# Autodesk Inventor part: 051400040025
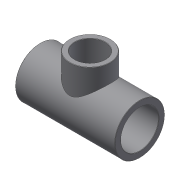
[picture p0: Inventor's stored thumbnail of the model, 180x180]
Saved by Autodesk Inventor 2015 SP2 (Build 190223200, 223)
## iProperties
Created: 2017-10
Part Number: 051400040025
Material: Generic
Description: PLASSON REDUCER TEE - CEMENT PVC 40-25-40
Document SubType Name: Modeling
Designer: KIM
Density: 1 g/cm^3
Appearance: Default
Author: KIM
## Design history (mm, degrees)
derived "051400.ipt"
feature "Solid1::051400.ipt"
feature "Solid2::051400.ipt"
tag "TaggingFeature1"
body "Solid1"
other parameters: "d0" = 99, "d2" = 26, "d5" = 32, "d7" = 0.4, "d8" = 26, "d9" = 41, "d10" = 37, "d11" = 25, "d12" = 22.5, "d23" = 24, "d24" = 0.4, "d26" = 0, "d30" = 0, "d32" = 0, "H_" = 99, "l_" = 26, "Z_" = 14, "E_1" = 37, "l_1" = 24, "Z_1" = 12.5, "H_1" = 66, "d_1" = 25
